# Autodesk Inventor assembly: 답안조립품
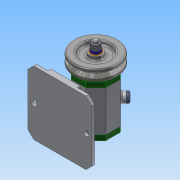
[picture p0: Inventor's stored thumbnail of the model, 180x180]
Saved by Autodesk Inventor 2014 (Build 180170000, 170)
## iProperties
Created: 2018-06
Part Number: 답안조립품
Document SubType Name: Assembly
Designer: SEO-12
Author: SEO-12
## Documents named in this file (16)
- C:\Users\SEO-12\Desktop\480608V1014\답안조립품.iam
- C:\Users\SEO-12\Desktop\480608V1014\본체.ipt
- C:\Users\SEO-12\Desktop\480608V1014\V벨트풀리.ipt
- C:\Users\SEO-12\Desktop\480608V1014\고무캡.ipt
- C:\Users\SEO-12\Desktop\480608V1014\너트 M8.ipt
- 너트 M8.ipt
- C:\Users\SEO-12\Desktop\480608V1014\뒤커버.ipt
- C:\Users\SEO-12\Desktop\480608V1014\베어링 15x32x9.ipt
- C:\Users\SEO-12\Desktop\480608V1014\볼트 M4x12.ipt
- C:\Users\SEO-12\Desktop\480608V1014\스프링와셔 8.ipt
- C:\Users\SEO-12\Desktop\480608V1014\앞커버.ipt
- C:\Users\SEO-12\Desktop\480608V1014\오일 실 15 25 7.ipt
- C:\Users\SEO-12\Desktop\480608V1014\와셔 8x17.ipt
- C:\Users\SEO-12\Desktop\480608V1014\축.ipt
- C:\Users\SEO-12\Desktop\480608V1014\키 3x3x12.ipt
- 키 3x3x12.ipt
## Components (2 placed, 2 different names)
1. V벨트풀리:1
2. 고무캡:1
